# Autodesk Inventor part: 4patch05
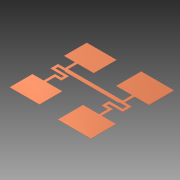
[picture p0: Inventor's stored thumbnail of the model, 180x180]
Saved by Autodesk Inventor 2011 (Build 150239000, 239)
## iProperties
Created: 2014-03
Part Number: 4patch05
Document SubType Name: Modeling
Designer: Evgeny
Density: 1 g/cm^3
Author: Evgeny
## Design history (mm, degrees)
sketch "Эскиз1"
  geometry: L1 (-65, 4.5)-(64.5, 4.5); L2 (64.5, -3)-(64.5, -4.5); L3 (64.5, -4.5)-(-64.5, -4.5); L4 (-64.5, -4.5)-(-64.5, -3); L5 (-71, 3)-(-81.5, 3); L6 (-81.5, -3)-(-64.5, -3); L7 (-71, 3)-(-71, 27); L8 (-71, 27)-(-65, 27); L9 (-65, 27)-(-65, 4.5); L10 (-81.5, 3)-(-87.5, 3); L11 (-87.5, 3)-(-87.5, -14); L12 (-81.5, -9)-(-81.5, -3); L13 (-81.5, -9)-(-49.5, -9); L14 (-49.5, -9)-(-49.5, -25); L15 (-55.5, -15)-(-87.5, -15); L16 (-87.5, -15)-(-87.5, -14); L17 (-55.5, -15)-(-55.5, -21); L18 (-56.5, -27)-(-49.5, -27); L19 (-49.5, -27)-(-49.5, -25); L20 (-56.5, -27)-(-64.5, -27); L21 (-70.5, -37)-(-70.5, -21); L22 (-70.5, -21)-(-55.5, -21); L23 (-70.5, -21)-(-66, -21); L24 (-64.5, -27)-(-64.5, -48); L25 (-64.5, -48)-(-70.5, -48); L26 (-70.5, -48)-(-70.5, -21); L27 (70.5, 3)-(87.5, 3); L28 (87.5, 3)-(87.5, -3); L29 (81.5, -3)-(64.5, -3); L30 (70.5, 3)-(70.5, 27); L31 (70.5, 27)-(64.5, 27); L32 (64.5, 27)-(64.5, 4.5); L33 (81.5, -3)-(81.5, -12.5); L34 (85.5, -18.5)-(87.5, -18.5); L35 (87.5, -18.5)-(87.5, -3); L36 (85.5, -18.5)-(55.5, -18.5); L37 (49.5, -15)-(49.5, -12.5); L38 (49.5, -12.5)-(81.5, -12.5); L39 (49.5, -12.5)-(55.5, -12.5); L40 (55.5, -18.5)-(55.5, -24.5); L41 (55.5, -30.5)-(49.5, -30.5); L42 (49.5, -30.5)-(49.5, -12.5); L43 (55.5, -30.5)-(64.5, -30.5); L44 (70.5, -27)-(70.5, -24.5); L45 (70.5, -24.5)-(55.5, -24.5); L46 (70.5, -24.5)-(65, -24.5); L47 (64.5, -30.5)-(64.5, -51.5); L48 (64.5, -51.5)-(70.5, -51.5); L49 (70.5, -51.5)-(70.5, -24.5); L50 (-97.1, 81)-(-26.5, 81); L51 (-26.5, 81)-(-26.5, 27); L52 (-26.5, 27)-(-97.1, 27); L53 (-97.1, 27)-(-97.1, 81); L54 (26.5, 86.5)-(104.5, 86.5); L55 (104.5, 86.5)-(104.5, 27); L56 (104.5, 27)-(26.5, 27); L57 (26.5, 27)-(26.5, 86.5); L58 (-97.1, -102)-(-26.5, -102); L59 (-26.5, -102)-(-26.5, -48); L60 (-26.5, -48)-(-97.1, -48); L61 (-97.1, -48)-(-97.1, -102); L62 (26.5, -111)-(104.5, -111); L63 (104.5, -111)-(104.5, -51.5); L64 (104.5, -51.5)-(26.5, -51.5)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; 1 further point
  constraints: 130 end point, 28 parallel, 15 horizontal, 14 perpendicular
  dimensions: "d0" = 129 distance between parallel lines of L2 L4; "d1" = 64.5 distance from line of point (0, 0) L4; "d2" = 9 distance between parallel lines of L3 L1; "d3" = 4.5 distance from line of point (0, 0) L3; "d5" = 6 distance between parallel lines of L5 L6; "d6" = 22.5 distance between parallel lines of L8 L1; "d7" = 6 distance between parallel lines of L7 L9; "d8" = 17 distance from line of L4.end L12; "d9" = 6 distance between parallel lines of L11 L12; "d10" = 6 distance between parallel lines of L13 L6; "d11" = 6 distance between parallel lines of L15 L13; "d12" = 15 distance between parallel lines of L19 L24; "d13" = 6 distance between parallel lines of L19 L17; "d14" = 6 distance between parallel lines of L20 L22; "d15" = 6 distance between parallel lines of L26 L24; "d16" = 27 distance between parallel lines of L25 L22; "d17" = 33 distance between parallel lines of L15 L25; "d18" = 64.5 distance from line of L24 point (0, 0); "d19" = 6 distance between parallel lines of L30 L32; "d20" = 17 distance between parallel lines of L33 L2; "d21" = 6 distance between parallel lines of L27 L29; "d22" = 6 distance between parallel lines of L35 L33; "d23" = 6 distance between parallel lines of L36 L38; "d24" = 6 distance between parallel lines of L49 L47; "d25" = 6 distance between parallel lines of L43 L45; "d26" = 6 distance between parallel lines of L42 L40; "d27" = 129 distance between parallel lines of L47 L24; "d28" = 15 distance between parallel lines of L42 L47; "d29" = 33 distance between parallel lines of L36 L48; "d30" = 27 distance between parallel lines of L45 L48; "d31" = 70.6 distance between parallel lines of L53 L51; "d32" = 54 distance between parallel lines of L52 L50; "d33" = 78 distance between parallel lines of L55 L57; "d34" = 59.5 distance between parallel lines of L56 L54; "d35" = 53 distance between parallel lines of L57 L51; "d36" = 26.5 distance from line of L57 point (0, 0); "d37" = 54 distance between parallel lines of L58 L60; "d38" = 70.6 distance between parallel lines of L59 L61; "d39" = 59.5 distance between parallel lines of L62 L64; "d40" = 78 distance between parallel lines of L63 L65; "d41" = 53 distance between parallel lines of L65 L59; "d42" = 26.5 distance from line of L59 point (0, 0); "d45" = 33 distance between parallel lines of L60 L15; "d46" = 33 distance between parallel lines of L64 L36
extrude "Выдавливание1" new body sketch "Эскиз1" distance "d43" = 0.5; taper "d44" = 0 deg
node "Твердое тело1"
